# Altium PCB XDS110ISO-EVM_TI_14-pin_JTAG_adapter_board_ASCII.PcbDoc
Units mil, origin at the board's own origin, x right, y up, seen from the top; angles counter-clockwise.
Board outline 1100 x 500 mil, 2 copper layers (Top Signal, Bottom Signal), stack 61.6 mil thick; 2 components, 6 nets, 29 pads, 12 vias.
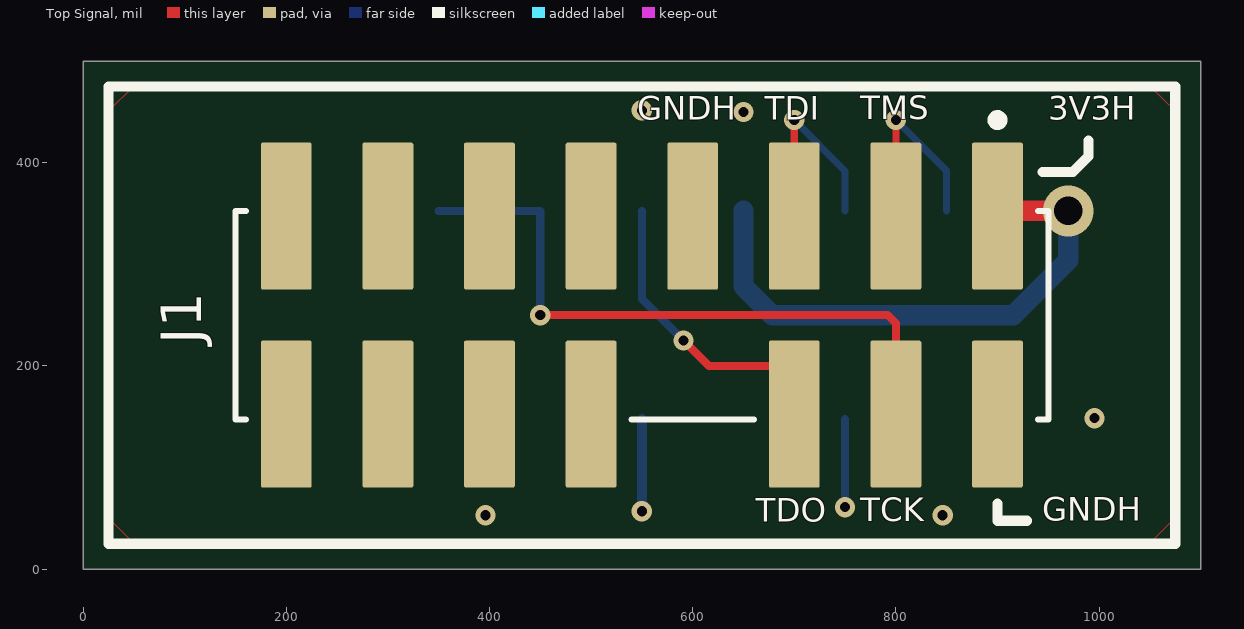
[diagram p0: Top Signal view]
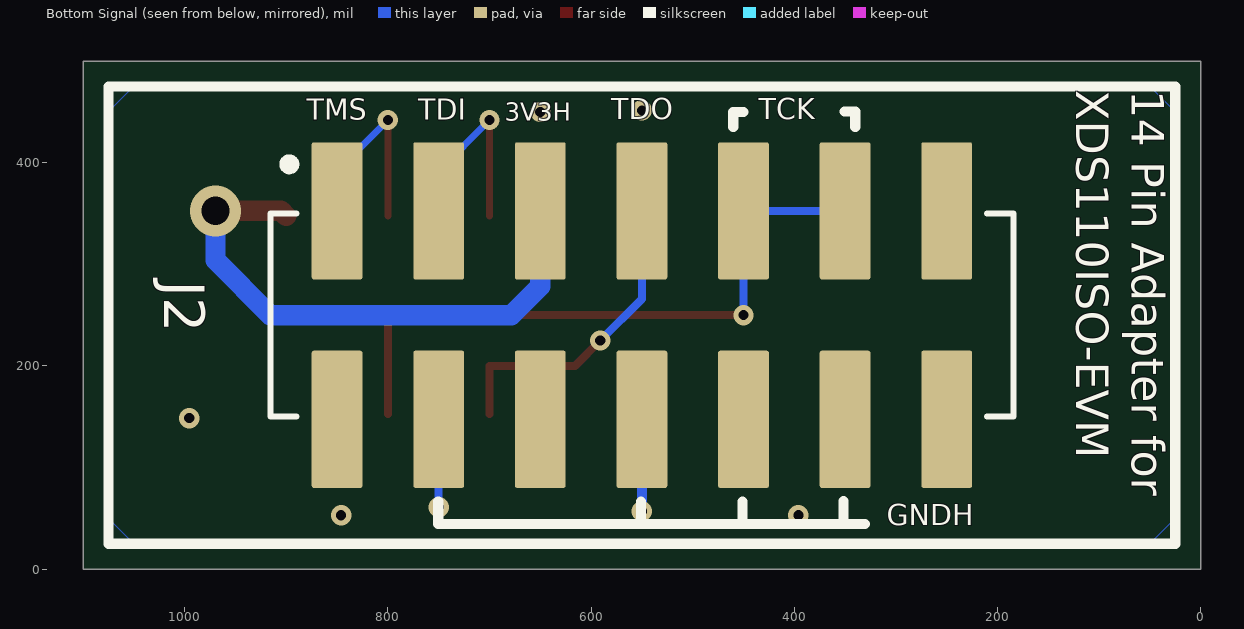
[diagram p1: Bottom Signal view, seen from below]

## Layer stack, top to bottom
Top Solder: solder mask 0.4, Solder Resist, Dk 3.5
Top Signal: signal copper 1.4
Dielectric 1: prepreg 8, FR-4, Dk 4.2
Dielectric 2: core 42.8, FR-4, Dk 4.2
Dielectric 3: prepreg 8, FR-4, Dk 4.2
Bottom Signal: signal copper 1.4
Bottom Solder: solder mask 0.4, Solder Resist, Dk 3.5

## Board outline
0,0 1100,0 1100,500 0,500

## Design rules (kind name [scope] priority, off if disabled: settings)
AcuteAngle [All] p0: scope1count=1 scope1_0_kind=Board scope1_0_value=Board scope2count=1 scope2_0_kind=Board scope2_0_value=Board commentlength=0 minimum=4.50000000000000E+0001
AcuteAngle [All] p1: minimum=4.50000000000000E+0001 checktracksonly=TRUE
AssemblyTestPointUsage [All] p0: scope1count=1 scope1_0_kind=Board scope1_0_value=Board scope2count=1 scope2_0_kind=Board scope2_0_value=Board commentlength=0
AssemblyTestPointUsage [All] p1: valid=2
AssemblyTestpoint [All] p0: scope1count=1 scope1_0_kind=Board scope1_0_value=Board scope2count=1 scope2_0_kind=Board scope2_0_value=Board commentlength=0
BoardOutlineClearance BoardOutlineClearance_USB101 [All] p0: scope1count=1 scope1_0_kind=Component scope1_0_value=USB101 scope2count=1 scope2_0_kind=Board scope2_0_value=Board commentlength=0 gap=0
BoardOutlineClearance [All] p0 off: scope1count=1 scope1_0_kind=Board scope1_0_value=Board scope2count=1 scope2_0_kind=Board scope2_0_value=Board commentlength=172 gap=10 // Protel DXP Scope 1 Expression Was: OnCopper and Not InComponentClass('Logo') and not InComponentClass('FiducialMark') and not InRegion(1000,500,4000,800) and not InPoly
BoardOutlineClearance BoardOutlineClearance_Poly [All] p0 off: scope1count=1 scope1_0_kind=Board scope1_0_value=Board scope2count=1 scope2_0_kind=Board scope2_0_value=Board commentlength=58 gap=25 // Protel DXP Scope 1 Expression Was: OnCopper and IsPoly
BoardOutlineClearance BoardOutlineClearance_MountingHoles [All] p0 off: scope1count=1 scope1_0_kind=Board scope1_0_value=Board scope2count=1 scope2_0_kind=Board scope2_0_value=Board commentlength=86 gap=40 // Protel DXP Scope 1 Expression Was: OnCopper and InComponentClass('Mounting Holes')
BoardOutlineClearance BoardOutlineClearance_MountingHoles [OnCopper and InComponentClass('Mounting Holes')] p1: gap=40 ignorepadtopadclearanceinfootprint=FALSE
BoardOutlineClearance BoardOutlineClearance_Poly [OnCopper and IsPoly] p2: gap=25 ignorepadtopadclearanceinfootprint=FALSE
BoardOutlineClearance BoardOutlineClearance_USB101 [InComponent('USB101')] p3: gap=0 ignorepadtopadclearanceinfootprint=FALSE
BoardOutlineClearance [OnCopper and Not InComponentClass('Logo') and not InComponentClass('FiducialMark') and not InRegion(1000,500,4000,800) and not InPoly] p4: gap=10 ignorepadtopadclearanceinfootprint=FALSE
Clearance Clearance_PTH [All] p0 off: scope1count=1 scope1_0_kind=Board scope1_0_value=Board scope2count=1 scope2_0_kind=Board scope2_0_value=Board commentlength=56 gap=7 // Protel DXP Scope 1 Expression Was: HoleDiameter > 10
Clearance Clearance_NPTH [All] p0 off: scope1count=1 scope1_0_kind=Board scope1_0_value=Board scope2count=1 scope2_0_kind=Board scope2_0_value=Board commentlength=56 gap=15 // Protel DXP Scope 1 Expression Was: HoleDiameter = 39
Clearance Clearance_FiducialMark [All] p0: scope1count=1 scope1_0_kind=ComponentClass scope1_0_value=FiducialMark scope2count=1 scope2_0_kind=ComponentClass scope2_0_value=FiducialMark commentlength=0 gap=0
Clearance Clearance_Boardedge [All] p0 off: scope1count=1 scope1_0_kind=Board scope1_0_value=Board scope2count=1 scope2_0_kind=Board scope2_0_value=Board commentlength=48 gap=11.8 // Protel DXP Scope 2 Expression Was: IsKeepOut
Clearance [All] p0: scope1count=1 scope1_0_kind=Board scope1_0_value=Board scope2count=1 scope2_0_kind=Board scope2_0_value=Board commentlength=0 gap=6
Clearance Clearance_NPTH [HoleDiameter = 39] p1: gap=15 ignorepadtopadclearanceinfootprint=FALSE
Clearance Clearance_PTH [HoleDiameter > 10] p2: gap=7 ignorepadtopadclearanceinfootprint=FALSE
Clearance Clearance_FiducialMark [InComponentClass('FiducialMark') vs InComponentClass('FiducialMark')] p3: gap=0 ignorepadtopadclearanceinfootprint=FALSE
Clearance Clearance_Boardedge [All vs IsKeepOut] p4: gap=11.8 ignorepadtopadclearanceinfootprint=FALSE
Clearance [All] p5: gap=6 ignorepadtopadclearanceinfootprint=FALSE
ComponentClearance ComponentClearance_THtoTH [All] p0 off: scope1count=1 scope1_0_kind=Board scope1_0_value=Board scope2count=1 scope2_0_kind=Board scope2_0_value=Board commentlength=54 gap=20 collisioncheckmode=3 // Protel DXP Scope 2 Expression Was: IsThruComponent
ComponentClearance ComponentClearance_THtoSMT [All] p0 off: scope1count=1 scope1_0_kind=Board scope1_0_value=Board scope2count=1 scope2_0_kind=Board scope2_0_value=Board commentlength=53 gap=10 collisioncheckmode=3 // Protel DXP Scope 2 Expression Was: IsSMTComponent
ComponentClearance ComponentClearance_SmallPassives [All] p0 off: scope1count=1 scope1_0_kind=Board scope1_0_value=Board scope2count=1 scope2_0_kind=Board scope2_0_value=Board commentlength=508 gap=10 collisioncheckmode=3 // Protel DXP Scope 2 Expression Was: HasFootprint('0201*') or HasFootprint('0402*') or HasFootprint('0508') or HasFootprint('0603*') or HasFootprint('0612') or HasFootprint('0805*') or HasFootprint('0815*') or HasFootprint('0830*') or HasFootprint('1206*') or HasFootprint('1210*') or HasFootprint('1808*') or HasFootprint('1812*') or HasFootprint('1825*') or HasFootprint('2010*') or HasFootprint('2220*') or HasFootprint('2225*') or HasFootprint('2512*') or HasFootprint('2728*') or HasFootprint('3518*')
ComponentClearance ComponentClearance_MountingHoles [All] p0 off: scope1count=1 scope1_0_kind=ComponentClass scope1_0_value="Mounting Holes" scope2count=1 scope2_0_kind=Board scope2_0_value=Board commentlength=0 gap=250 collisioncheckmode=3
ComponentClearance ComponentClearance_ScrewToNut [All] p0 off: scope1count=1 scope1_0_kind=Board scope1_0_value=Board scope2count=1 scope2_0_kind=Board scope2_0_value=Board commentlength=71 gap=3.94 collisioncheckmode=3 // Protel DXP Scope 2 Expression Was: (HasFootprint('Keystone_1902C'))
ComponentClearance ComponentClearance_Logo [All] p0: scope1count=1 scope1_0_kind=ComponentClass scope1_0_value=Logo scope2count=1 scope2_0_kind=Board scope2_0_value=Board commentlength=0 gap=0 collisioncheckmode=3
ComponentClearance ComponentClearance_Shunt [All] p0: scope1count=1 scope1_0_kind=ComponentClass scope1_0_value=Header scope2count=1 scope2_0_kind=ComponentClass scope2_0_value=Shunt commentlength=0 gap=0 collisioncheckmode=3
ComponentClearance ComponentClearance_MountingHoles_FiducialMarks [All] p0: scope1count=1 scope1_0_kind=ComponentClass scope1_0_value="Mounting Holes" scope2count=1 scope2_0_kind=ComponentClass scope2_0_value=FiducialMark commentlength=0 gap=50 collisioncheckmode=3
ComponentClearance ComponentClearance_Logo_1 [All] p0: scope1count=1 scope1_0_kind=ComponentClass scope1_0_value=Logo scope2count=1 scope2_0_kind=ComponentClass scope2_0_value=Logo commentlength=0 gap=0 collisioncheckmode=3
ComponentClearance "ComponentClearance_overlay to overlay" [All] p0 off: scope1count=1 scope1_0_kind=Board scope1_0_value=Board scope2count=1 scope2_0_kind=Board scope2_0_value=Board commentlength=54 gap=0 collisioncheckmode=3 // Protel DXP Scope 2 Expression Was: OnTopSilkscreen
ComponentClearance "ComponentClearance_overlay to overlay" [OnBottomSilkscreen vs OnTopSilkscreen] p1: gap=0 collisioncheckmode=3 verticalgap=0 showdistances=FALSE
ComponentClearance ComponentClearance_MountingHoles_FiducialMarks [InComponentClass('Mounting Holes') vs InComponentClass('FiducialMark')] p2: gap=50 collisioncheckmode=3 verticalgap=10 showdistances=FALSE
ComponentClearance ComponentClearance_Shunt [InComponentClass('Header') vs InComponentClass('Shunt')] p3: gap=0 collisioncheckmode=3 verticalgap=0 showdistances=FALSE
ComponentClearance ComponentClearance_Logo [InComponentClass('Logo')] p4: gap=0 collisioncheckmode=3 verticalgap=0 showdistances=FALSE
ComponentClearance ComponentClearance_Logo_1 [InComponentClass('Logo') vs InComponentClass('Logo')] p5: gap=0 collisioncheckmode=3 verticalgap=0 showdistances=FALSE
ComponentClearance ComponentClearance_ScrewToNut [(HasFootprint('NY PMS 440 0025 PH')) vs (HasFootprint('Keystone_1902C'))] p6: gap=3.94 collisioncheckmode=3 verticalgap=3.94 showdistances=FALSE
ComponentClearance ComponentClearance_MountingHoles [InComponentClass('Mounting Holes')] p7 off: gap=250 collisioncheckmode=3 verticalgap=100000 showdistances=FALSE
ComponentClearance ComponentClearance_SmallPassives [HasFootprint('0201*') or HasFootprint('0402*') or HasFootprint('0508') or HasFootprint('0603*') or HasFootprint('0612') or HasFootprint('0805*') or HasFootprint('0815*') or HasFootprint('0830*') or HasFootprint('1206*') or HasFootprint('1210*') or HasFootprint('1808*') or HasFootprint('1812*') or HasFootprint('1825*') or HasFootprint('2010*') or HasFootprint('2220*') or HasFootprint('2225*') or HasFootprint('2512*') or HasFootprint('2728*') or HasFootprint('3518*') vs HasFootprint('0201*') or HasFootprint('0402*') or HasFootprint('0508') or HasFootprint('0603*') or HasFootprint('0612') or HasFootprint('0805*') or HasFootprint('0815*') or HasFootprint('0830*') or HasFootprint('1206*') or HasFootprint('1210*') or HasFootprint('1808*') or HasFootprint('1812*') or HasFootprint('1825*') or HasFootprint('2010*') or HasFootprint('2220*') or HasFootprint('2225*') or HasFootprint('2512*') or HasFootprint('2728*') or HasFootprint('3518*')] p8 off: gap=10 collisioncheckmode=3 verticalgap=0 showdistances=FALSE
ComponentClearance ComponentClearance_THtoSMT [IsThruComponent vs IsSMTComponent] p9 off: gap=10 collisioncheckmode=3 verticalgap=10 showdistances=FALSE
ComponentClearance ComponentClearance_THtoTH [IsThruComponent vs IsThruComponent] p10 off: gap=20 collisioncheckmode=3 verticalgap=30 showdistances=FALSE
DiffPairsRouting [All] p0: scope1count=1 scope1_0_kind=Board scope1_0_value=Board scope2count=1 scope2_0_kind=Board scope2_0_value=Board commentlength=0
DiffPairsRouting [All] p1: maxlimit=100 minlimit=6 mostfreqgap=6 toplayer_minwidth=5.91 toplayer_maxwidth=15 toplayer_prefwidth=10.63 bottomlayer_minwidth=5.91 bottomlayer_maxwidth=15 bottomlayer_prefwidth=10.63 maxuncoupledlength=1000
FabricationTestPointUsage TestPointUsage [All] p0: scope1count=1 scope1_0_kind=Board scope1_0_value=Board scope2count=1 scope2_0_kind=Board scope2_0_value=Board commentlength=0 valid=2 allowmultiple=FALSE
FabricationTestPointUsage TestPointUsage [All] p1: valid=2 allowmultiple=FALSE
FabricationTestpoint Testpoint [All] p0: scope1count=1 scope1_0_kind=Board scope1_0_value=Board scope2count=1 scope2_0_kind=Board scope2_0_value=Board commentlength=0 side=3 testpointundercomponent=TRUE minsize=40 maxsize=100 preferedsize=60 minholesize=0 maxholesize=40 preferedholesize=32 testpointgrid=1
FabricationTestpoint Testpoint [All] p1: side=3 testpointundercomponent=TRUE minsize=40 maxsize=100 preferedsize=60 minholesize=0 maxholesize=40 preferedholesize=32 testpointgrid=1 allowsidetop=TRUE allowsidebottom=TRUE usegrid=TRUE gridtolerance=0.01
FanoutControl Fanout_Small [All] p0 off: scope1count=1 scope1_0_kind=Board scope1_0_value=Board scope2count=1 scope2_0_kind=Board scope2_0_value=Board commentlength=84 // Protel DXP Scope 1 Expression Was: (CompPinCount < 5)   Fanout_Small (Default Rule)
FanoutControl Fanout_Default [All] p0: scope1count=1 scope1_0_kind=Board scope1_0_value=Board scope2count=1 scope2_0_kind=Board scope2_0_value=Board commentlength=30 // Fanout_Default (Default Rule)
FanoutControl Fanout_SOIC [All] p0 off: scope1count=1 scope1_0_kind=Board scope1_0_value=Board scope2count=1 scope2_0_kind=Board scope2_0_value=Board commentlength=71 // Protel DXP Scope 1 Expression Was: IsSOIC   Fanout_SOIC (Default Rule)
FanoutControl Fanout_BGA [All] p0 off: scope1count=1 scope1_0_kind=Board scope1_0_value=Board scope2count=1 scope2_0_kind=Board scope2_0_value=Board commentlength=69 // Protel DXP Scope 1 Expression Was: IsBGA   Fanout_BGA (Default Rule)
FanoutControl Fanout_LCC [All] p0 off: scope1count=1 scope1_0_kind=Board scope1_0_value=Board scope2count=1 scope2_0_kind=Board scope2_0_value=Board commentlength=69 // Protel DXP Scope 1 Expression Was: IsLCC   Fanout_LCC (Default Rule)
FanoutControl Fanout_LCC [IsLCC] p1: bgadir=Out bgaviamode=Centered fanoutstyle=Auto fanoutdirection=Alternating viagrid=1 // Fanout_LCC (Default Rule)
FanoutControl Fanout_BGA [IsBGA] p2: bgadir=Out bgaviamode=Centered fanoutstyle=Auto fanoutdirection=Alternating viagrid=1 // Fanout_BGA (Default Rule)
FanoutControl Fanout_Default [All] p4: bgadir=Out bgaviamode=Centered fanoutstyle=Auto fanoutdirection=Alternating viagrid=1 // Fanout_Default (Default Rule)
FanoutControl Fanout_Small [(CompPinCount < 5)] p5: bgadir=Out bgaviamode=Centered fanoutstyle=Auto fanoutdirection=OutThenIn viagrid=1 // Fanout_Small (Default Rule)
Height [All] p0: scope1count=1 scope1_0_kind=Board scope1_0_value=Board scope2count=1 scope2_0_kind=Board scope2_0_value=Board commentlength=0
HoleSize [All] p0: scope1count=1 scope1_0_kind=Board scope1_0_value=Board scope2count=1 scope2_0_kind=Board scope2_0_value=Board commentlength=0 absolutevalues=TRUE maxlimit=251 minlimit=7.87 maxpercent=80.000 minpercent=20.000
HoleSize [All] p1: absolutevalues=TRUE maxlimit=251 minlimit=7.87 maxpercent=80.000 minpercent=20.000
HoleToHoleClearance HoleToHoleClearance_USB101 [All] p0: scope1count=1 scope1_0_kind=Component scope1_0_value=USB101 scope2count=1 scope2_0_kind=Component scope2_0_value=USB101 commentlength=0
HoleToHoleClearance [All] p0: scope1count=1 scope1_0_kind=Board scope1_0_value=Board scope2count=1 scope2_0_kind=Board scope2_0_value=Board commentlength=0
HoleToHoleClearance HoleToHoleClearance_USB101 [InComponent('USB101') vs InComponent('USB101')] p1: gap=0 allowstackedmicrovias=TRUE
HoleToHoleClearance [All] p2: gap=12 allowstackedmicrovias=TRUE
LayerPairs [All] p0: scope1count=1 scope1_0_kind=Board scope1_0_value=Board scope2count=1 scope2_0_kind=Board scope2_0_value=Board commentlength=0 enforce=TRUE
MatchedLengths FSIRX [All] p0: scope1count=1 scope1_0_kind=NetClass scope1_0_value=FSIRX scope2count=1 scope2_0_kind=Board scope2_0_value=Board commentlength=0 tolerance=25 amplitude=200 gap=20 style=90-Degree
MatchedLengths FSITX [All] p0: scope1count=1 scope1_0_kind=NetClass scope1_0_value=FSITX scope2count=1 scope2_0_kind=Board scope2_0_value=Board commentlength=0 tolerance=25 amplitude=200 gap=20 style=90-Degree
MatchedLengths FSIRX [InNetClass('FSIRX')] p1: tolerance=25 checknetsindiffpair=FALSE checkdiffpairvsdiffpair=TRUE checkxsignals=TRUE checkothers=TRUE
MatchedLengths FSITX [InNetClass('FSITX')] p2: tolerance=25 checknetsindiffpair=FALSE checkdiffpairvsdiffpair=TRUE checkxsignals=TRUE checkothers=TRUE
MinimumAnnularRing [All] p0: scope1count=1 scope1_0_kind=Board scope1_0_value=Board scope2count=1 scope2_0_kind=Board scope2_0_value=Board commentlength=0 minimumring=5
MinimumAnnularRing MinimumAnnularRing_ThermalPadVias [All] p0 off: scope1count=1 scope1_0_kind=Board scope1_0_value=Board scope2count=1 scope2_0_kind=Board scope2_0_value=Board commentlength=63 minimumring=5 // Protel DXP Scope 1 Expression Was: IsVia and InAnyComponent
MinimumAnnularRing MinimumAnnularRing_ThermalPadVias [IsVia and InAnyComponent] p1: minimumring=5
MinimumAnnularRing [All] p2: minimumring=5
MinimumSolderMaskSliver [All] p0: scope1count=1 scope1_0_kind=Board scope1_0_value=Board scope2count=1 scope2_0_kind=Board scope2_0_value=Board commentlength=0
MinimumSolderMaskSliver MinimumSolderMaskSliver_Logo [All] p0: scope1count=1 scope1_0_kind=ComponentClass scope1_0_value=Logo scope2count=1 scope2_0_kind=ComponentClass scope2_0_value=Logo commentlength=0
MinimumSolderMaskSliver MinimumSolderMaskSliver_Logo [InComponentClass('Logo') vs InComponentClass('Logo')] p1: minsoldermaskwidth=0.7
MinimumSolderMaskSliver [All] p2: minsoldermaskwidth=0
NetAntennae [All] p0: scope1count=1 scope1_0_kind=Board scope1_0_value=Board scope2count=1 scope2_0_kind=Board scope2_0_value=Board commentlength=0
PasteMaskExpansion [All] p0: scope1count=1 scope1_0_kind=Board scope1_0_value=Board scope2count=1 scope2_0_kind=Board scope2_0_value=Board commentlength=0 expansion=0
PlaneClearance [All] p0: scope1count=1 scope1_0_kind=Board scope1_0_value=Board scope2count=1 scope2_0_kind=Board scope2_0_value=Board commentlength=0 clearance=6
PlaneClearance [All] p1: clearance=6
PlaneConnect [All] p0: scope1count=1 scope1_0_kind=Board scope1_0_value=Board scope2count=1 scope2_0_kind=Board scope2_0_value=Board commentlength=0 planeconnectstyle=Relief reliefexpansion=7 reliefentries=4 reliefconductorwidth=8 reliefairgap=6
PlaneConnect [All] p1: planeconnectstyle=Relief reliefexpansion=7 reliefentries=4 reliefconductorwidth=8 reliefairgap=6
PolygonConnect PolygonConnect_GNDH [All] p0 off: scope1count=1 scope1_0_kind=Board scope1_0_value=Board scope2count=1 scope2_0_kind=Board scope2_0_value=Board commentlength=70 connectstyle=Relief reliefconductorwidth=30 reliefentries=4 polygonreliefangle="90 Angle" // Protel DXP Scope 1 Expression Was: InNet('GNDH') OR InNet('+3V3H')
PolygonConnect PolygonConnect_via [All] p0 off: scope1count=1 scope1_0_kind=Board scope1_0_value=Board scope2count=1 scope2_0_kind=Board scope2_0_value=Board commentlength=44 connectstyle=Relief reliefconductorwidth=8 reliefentries=4 polygonreliefangle="90 Angle" // Protel DXP Scope 1 Expression Was: isvia
PolygonConnect [All] p0: scope1count=1 scope1_0_kind=Board scope1_0_value=Board scope2count=1 scope2_0_kind=Board scope2_0_value=Board commentlength=0 connectstyle=Relief reliefconductorwidth=8 reliefentries=4 polygonreliefangle="90 Angle"
PolygonConnect PolygonConnect_via [isvia] p1: connectstyle=Relief reliefconductorwidth=8 reliefentries=4 polygonreliefangle="90 Angle" airgapwidth=6
PolygonConnect PolygonConnect_GNDH [InNet('GNDH') OR InNet('+3V3H')] p2: connectstyle=Relief reliefconductorwidth=30 reliefentries=4 polygonreliefangle="90 Angle" airgapwidth=6
PolygonConnect [All] p3: connectstyle=Relief reliefconductorwidth=8 reliefentries=4 polygonreliefangle="90 Angle" airgapwidth=6
RoutingCorners [All] p0: scope1count=1 scope1_0_kind=Board scope1_0_value=Board scope2count=1 scope2_0_kind=Board scope2_0_value=Board commentlength=0 cornerstyle=45-Degree minsetback=100 maxsetback=100
RoutingLayers [All] p0: scope1count=1 scope1_0_kind=Board scope1_0_value=Board scope2count=1 scope2_0_kind=Board scope2_0_value=Board commentlength=0 top layer=Automatic bottom layer=Automatic
RoutingPriority [All] p0: scope1count=1 scope1_0_kind=Board scope1_0_value=Board scope2count=1 scope2_0_kind=Board scope2_0_value=Board commentlength=0
RoutingTopology [All] p0: scope1count=1 scope1_0_kind=Board scope1_0_value=Board scope2count=1 scope2_0_kind=Board scope2_0_value=Board commentlength=0 topology=Shortest
RoutingVias RoutingVias_PWR [All] p0: scope1count=1 scope1_0_kind=Net scope1_0_value=+3V3H scope2count=1 scope2_0_kind=Board scope2_0_value=Board commentlength=0 holewidth=28 width=50 viastyle="Through Hole" minholewidth=28 minwidth=50 maxholewidth=28 maxwidth=50
RoutingVias [All] p0: scope1count=1 scope1_0_kind=Board scope1_0_value=Board scope2count=1 scope2_0_kind=Board scope2_0_value=Board commentlength=0 holewidth=10 width=20 viastyle="Through Hole" minholewidth=10 minwidth=20 maxholewidth=20 maxwidth=40
RoutingVias ThermalPadVias [All] p0: scope1count=1 scope1_0_kind=Board scope1_0_value=Board scope2count=1 scope2_0_kind=Board scope2_0_value=Board commentlength=0 holewidth=10 width=20 viastyle="Through Hole" minholewidth=10 minwidth=20 maxholewidth=20 maxwidth=40
RoutingVias RoutingVias_PWR [InNet('+3V3H')] p1: holewidth=28 width=50 viastyle="Through Hole" minholewidth=28 minwidth=50 maxholewidth=28 maxwidth=50
RoutingVias ThermalPadVias [All] p2: holewidth=10 width=20 viastyle="Through Hole" minholewidth=10 minwidth=20 maxholewidth=20 maxwidth=40
RoutingVias [All] p3: holewidth=10 width=20 viastyle="Through Hole" minholewidth=10 minwidth=20 maxholewidth=20 maxwidth=40
ShortCircuit [All] p0: scope1count=1 scope1_0_kind=Board scope1_0_value=Board scope2count=1 scope2_0_kind=Board scope2_0_value=Board commentlength=0 allowed=FALSE
SilkToBoardRegionClearance [All] p0 off: scope1count=1 scope1_0_kind=Board scope1_0_value=Board scope2count=1 scope2_0_kind=Board scope2_0_value=Board commentlength=130 // Protel DXP Scope 1 Expression Was: Not ((IsComment or IsDesignator) And (Hide <> 'False')) and not InRegion(1000,500,4000,800)
SilkToBoardRegionClearance [Not ((IsComment or IsDesignator) And (Hide <> 'False')) and not InRegion(1000,500,4000,800)] p1:
SilkToSilkClearance [All] p0: scope1count=1 scope1_0_kind=Board scope1_0_value=Board scope2count=1 scope2_0_kind=Board scope2_0_value=Board commentlength=0
SilkToSilkClearance SilkToSilkClearance_Pb-FreeLogo [All] p0 off: scope1count=1 scope1_0_kind=Board scope1_0_value=Board scope2count=1 scope2_0_kind=Board scope2_0_value=Board commentlength=120 // Protel DXP Scope 2 Expression Was: (HasFootprint('Pb-Free_Overlay_Medium') OR HasFootprint('Pb-Free_Overlay_Small'))
SilkToSilkClearance SilkToSilkClearance_Pb-FreeLogo [(HasFootprint('Pb-Free_Overlay_Medium') OR HasFootprint('Pb-Free_Overlay_Small')) vs (HasFootprint('Pb-Free_Overlay_Medium') OR HasFootprint('Pb-Free_Overlay_Small'))] p1: silktosilkclearance=0
SilkToSilkClearance [All] p2: silktosilkclearance=3
SilkToSolderMaskClearance "Silk to Solder Mask Opening" [All] p0: scope1count=1 scope1_0_kind=Board scope1_0_value=Board scope2count=1 scope2_0_kind=Board scope2_0_value=Board commentlength=0
SilkToSolderMaskClearance SilkToComponentPadClearance [All] p0 off: scope1count=1 scope1_0_kind=Board scope1_0_value=Board scope2count=1 scope2_0_kind=Board scope2_0_value=Board commentlength=87 // Protel DXP Scope 1 Expression Was: (IsPad or IsFill or IsRegion) and InAnycomponent
SilkToSolderMaskClearance SilkToComponentPadClearance [(IsPad or IsFill or IsRegion) and InAnycomponent] p1: minsilkscreentomaskgap=2.5 clearancetoexposedcopper=TRUE
SilkToSolderMaskClearance "Silk to Solder Mask Opening" [All] p2: minsilkscreentomaskgap=2.5 clearancetoexposedcopper=TRUE
SolderMaskExpansion [All] p0: scope1count=1 scope1_0_kind=Board scope1_0_value=Board scope2count=1 scope2_0_kind=Board scope2_0_value=Board commentlength=0 expansion=2
SolderMaskExpansion [All] p1: expansion=2 istentingtop=FALSE
UnRoutedNet [All] p0: scope1count=1 scope1_0_kind=Board scope1_0_value=Board scope2count=1 scope2_0_kind=Board scope2_0_value=Board commentlength=0
UnRoutedNet [All] p1: checkbadconnections=TRUE
UnpouredPolygon [All] p0: scope1count=1 scope1_0_kind=Board scope1_0_value=Board scope2count=1 scope2_0_kind=Board scope2_0_value=Board commentlength=0
Width [All] p0: scope1count=1 scope1_0_kind=Board scope1_0_value=Board scope2count=1 scope2_0_kind=Board scope2_0_value=Board commentlength=0 maxlimit=100 minlimit=7 preferedwidth=8
Width Analog [All] p0: scope1count=1 scope1_0_kind=NetClass scope1_0_value=Analog scope2count=1 scope2_0_kind=Board scope2_0_value=Board commentlength=0 maxlimit=25 minlimit=8 preferedwidth=8
Width Analog [InNetClass('Analog')] p1: maxlimit=25 minlimit=8 preferedwidth=8
Width [All] p2: maxlimit=100 minlimit=7 preferedwidth=8 minimp=50.000000 maximp=50.000000 favimp=50.000000 checkconnectedcopper=TRUE
12 further rules are at their usual default settings.

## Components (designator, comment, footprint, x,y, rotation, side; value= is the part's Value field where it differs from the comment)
J1 "TSM-108-01-L-DV-008-P-TR" FP-TSM-108-01-L-DV-008-P-TR_HDR15-MFG 550,250 r180 top
J2 "SSW-107-22-G-D-VS-006" FP-SSW-107-22-G-D-VS-006_HDR14-MFG 550,250 r180 bottom

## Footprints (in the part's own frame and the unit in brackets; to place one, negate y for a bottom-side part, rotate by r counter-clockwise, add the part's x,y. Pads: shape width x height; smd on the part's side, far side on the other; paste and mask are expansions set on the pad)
FP-SSW-107-22-G-D-VS-006_HDR14-MFG [mm]
  rrect8% 1.27x3.43 smd paste+0 mask+0: 1(-7.62,2.605) 2(-7.62,-2.605) 3(-5.08,2.605) 4(-5.08,-2.605) 5(-2.54,2.605) 6(-2.54,-2.605) 7(0,2.605) 8(0,-2.605) 9(2.54,2.605) 10(2.54,-2.605) 11(5.08,2.605) 12(5.08,-2.605) 13(7.62,2.605) 14(7.62,-2.605)
  silkscreen extent -9.29,-2.54 9.29,3.89
FP-TSM-108-01-L-DV-008-P-TR_HDR15-MFG [mm]
  rrect8% 1.27x3.68 smd paste+0 mask+0: 1(-8.89,-2.475) 2(-8.89,2.475) 3(-6.35,-2.475) 4(-6.35,2.475) 5(-3.81,-2.475) 6(-3.81,2.475) 7(-1.27,-2.475) 9(1.27,-2.475) 10(1.27,2.475) 11(3.81,-2.475) 12(3.81,2.475) 13(6.35,-2.475) 14(6.35,2.475) 15(8.89,-2.475) 16(8.89,2.475)
  silkscreen extent -10.16,-5 10.16,2.6

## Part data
J1: library part CMP-0121706-1, "Conn Unshrouded HDR 16 POS 2.54mm Solder ST SMT"
J2: library part CMP-0121832-1, "14 Position Receptacle Connector 0.100\" (2.54mm) Surface Mount Gold"

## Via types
v1: diameter 20, hole 10, Top Signal to Bottom Signal, tented both sides, 11 vias
v2: diameter 50, hole 28, Top Signal to Bottom Signal, tented both sides, 1 vias

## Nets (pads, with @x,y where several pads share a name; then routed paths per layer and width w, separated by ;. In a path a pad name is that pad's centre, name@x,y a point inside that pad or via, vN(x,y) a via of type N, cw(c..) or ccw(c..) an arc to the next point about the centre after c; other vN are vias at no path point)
+3V3H: J1.1 J2.5 | length 548.3
  Top Signal w20: J1.1 905.12,352.56 v2(969.65,352.56)
  Bottom Signal w20: J2.5 650,278.51 678.53,249.99 915.73,249.99 969.65,303.9 v2(969.65,352.56)
GNDH: J1.2 J1.7 J2.4 J2.8 J2.10 J2.12 | length 176.9
  Bottom Signal w8: v1(750,60.99) J2.4
  Bottom Signal w10: v1(550,56.98) J2.8
  other v1: 396,52.99 846,52.99 995.47,148.56 650,449.93 550,451.49
MCU_TCK: J1.4 J2.9 J2.11 | length 645.3
  Top Signal w8: v1(450,249.99) 791.96,249.99 800,241.94 J1.4
  Bottom Signal w8: J2.11 J2.9 v1(450,249.99)
MCU_TDI: J1.5 J2.3 | length 204.6
  Top Signal w7: J1.5 v1(700,441.93)
  Bottom Signal w7: v1(700,441.93) 750,391.93 J2.3
MCU_TDO: J1.6 J2.7 | length 311.3
  Top Signal w8: v1(591,224.99) 616,199.99 700,199.99 J1.6
  Bottom Signal w8: J2.7 550,265.99 v1(591,224.99)
MCU_TMS: J1.3 J2.1 | length 204.6
  Top Signal w7: J1.3 v1(800,441.93)
  Bottom Signal w7: v1(800,441.93) 850,391.93 J2.1
pads on no net: J1.9 J1.10 J1.11 J1.12 J1.13 J1.14 J1.15 J1.16 J2.2 J2.6 J2.13 J2.14

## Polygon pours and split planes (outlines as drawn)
GNDH on Bottom Signal "NONET_L-01_P-001" (solid, remove dead copper, pour order 22): 1050,475 50,475 25,450 25,50 50,25 1050,25 1075,50 1075,450
GNDH on Top Signal "NONET_L-01_P-001" (solid, remove dead copper, pour order 15): 50,475 25,450.81 25,50.49 50,25.49 1050,25.49 1075,50.49 1075.22,450.81 1050,475

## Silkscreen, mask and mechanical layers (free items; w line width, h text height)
Top Overlay:
  lines w10: 900,64.38 900,47.63 928.89,47.63 ; 944.39,390.81 974.21,390.81 989.65,406.25 989.65,421.82 ; 25,25 1075,25 1075,475 25,475 25,25
  text "TMS" at 765,434.8 h40
  text "GNDH" at 545.56,434.3 h40
  text "TDI" at 670.72,434.3 h40
  text "3V3H" at 950,434.3 h40
  text "GNDH" at 943.94,39.64 h40
  text "TDO" at 662.24,38.73 h40
  text "TCK" at 765,39.22 h40
Bottom Overlay:
  lines w10: 25,474.51 25,25 1075,25 1075,474.51 ; 25,475 1075,475 ; 330.28,44.53 750.44,44.53 750.44,66.4 ; 340,435.31 340,450.31 350.62,450.31 ; 351.51,44.53 351.51,66.91 ; 450,450 460,450 460,435 ; 451,44.53 451,66.4 ; 551,44.53 551,66.4
  text "14 Pin Adapter for / XDS110ISO-EVM" at 133.51,471.48 h55 r90
  text "TCK" at 435,436.05 h35
  text "TDO" at 580,435.68 h35
  text "3V3H" at 685,435.31 h30
  text "TDI" at 770,435.43 h35
  text "TMS" at 880,435.43 h35
  text "GNDH" at 309,36.37 h35
M1 Board Outline:
  the board outline again, w10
